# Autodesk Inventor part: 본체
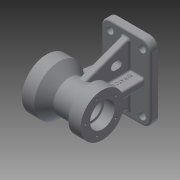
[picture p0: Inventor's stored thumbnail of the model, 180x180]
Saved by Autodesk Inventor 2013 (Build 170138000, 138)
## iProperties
Created: 2015-08
Part Number: 본체
Material: 알루미늄 6061
Document SubType Name: Modeling
Designer: dfdfd
Density: 2.71 g/cm^3
Mass: 1068.68 g
Surface Area: 796.751 cm^2
Volume: 394.348 cm^3
Author: dfdfd
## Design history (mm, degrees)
sketch "스케치2"
  geometry: L1 (0, 0)-(0, 35); L2 (0, 35)-(20, 35); L3 (20, 35)-(25.196, 26); L4 (25.196, 26)-(53.315, 26); L5 (53.315, 26)-(70, 40); L6 (70, 40)-(90, 40); L7 (90, 40)-(90, 0); L8 (90, 0)-(0, 0)
  constraints: 16 end point, 4 parallel, 1 perpendicular, 1 vertical
  dimensions: "d0" = 20 distance from line of L2.end L1; "d2" = 90 distance between parallel lines of L7 L1; "d3" = 20 distance from line of L7 L5.end; "d4" = 60 deg angle of L4 L3; "d5" = 40 deg angle of L4 L5; "d6" = 70 diameter of L2 L8; "d7" = 80 diameter of L6 L8; "d8" = 52 diameter of L4 L8
revolve "회전1" sketch "스케치2" stored, may be unused: angle "d9" = 90 deg
sketch "스케치3"
  geometry: L1 (0, 90)-(-80, 90); L2 (-80, 90)-(-80, 78); L3 (-80, 78)-(0, 78); L4 (0, 78)-(0, 90); L5 (0, -35)-(-20, -35) reference; L6 (-20, -35)-(-25.196, -26) reference; L7 (-25.196, -26)-(-53.315, -26) reference; L8 (-53.315, -26)-(-70, -40) reference; L9 (-70, -40)-(-90, -40) reference; L10 (-90, -40)-(-90, 40) reference; L11 (-90, 40)-(-70, 40) reference; L12 (-70, 40)-(-53.315, 26) reference; L13 (-53.315, 26)-(-25.196, 26) reference; L14 (-25.196, 26)-(-20, 35) reference; L15 (-20, 35)-(0, 35) reference; L16 (0, 35)-(0, -35) reference; 3 further points
  constraints: 8 end point, 2 midpoint, 2 parallel, 1 horizontal, 1 perpendicular, 1 vertical alignment
  dimensions: "d10" = 90 distance from line of L1 point (0, 0); "d11" = 12 distance between parallel lines of L1 L3; "d12" = 80 distance between parallel lines of L2 L4
extrude "돌출1" join sketch "스케치3" stored distance "d13" = 122; taper "d14" = 0 deg
sketch "스케치4"
  geometry: L1 (0, -35)-(-20, -35) reference; L2 (-20, -35)-(-25.196, -26) reference; L3 (-25.196, -26)-(-53.315, -26) reference; L4 (-53.315, -26)-(-70, -40) reference; L5 (-70, -40)-(-90, -40) reference; L6 (-90, -40)-(-90, 40) reference; L7 (-90, 40)-(-70, 40) reference; L8 (-70, 40)-(-53.315, 26) reference; L9 (-53.315, 26)-(-25.196, 26) reference; L10 (-25.196, 26)-(-20, 35) reference; L11 (-20, 35)-(0, 35) reference; L12 (0, 35)-(0, -35) reference; L13 (0, 90)-(0, 78) reference; L14 (0, 78)-(-80, 78) reference; L15 (-80, 78)-(-80, 90) reference; L16 (-80, 90)-(0, 90) reference; L17 (-70, 78)-(-76.7, 40); L18 (-10, 35)-(-10, 78); 1 further point
  constraints: 4 end point, 3 point on line, 1 midpoint, 1 perpendicular
  dimensions: "d17" = 10 distance between parallel lines of L13 L18; "d18" = 80 deg angle of L14 L17; "d19" = 10 distance from line of L15 L17.start
extrude "돌출2" join sketch "스케치4" stored distance "d20" = 12; taper "d21" = 0 deg
node "작업 평면1"
sketch "스케치5"
  geometry: L1 (90, -61)-(78, -61) reference; L2 (78, -61)-(78, -6) reference; L3 (78, -6)-(26, -6) reference; L4 (26, -6)-(26, 0) reference; L5 (26, 0)-(26, 6) reference; L6 (26, 6)-(78, 6) reference; L7 (78, 6)-(78, 61) reference; L8 (78, 61)-(90, 61) reference; L9 (90, 61)-(90, -61) reference; L10 (6.815, -25.091)-(78, -51); L11 (6.815, 25.091)-(78, 51); L12 (0, 0)-(113.141, 0); A1 r 26 centre (0, 0) between (26, 0) and (6.815, -25.091) reference; 1 further point
  constraints: 6 end point, 2 point on circle, 2 point on line, 1 perpendicular
  dimensions: "d23" = 70 deg angle of L11 L7; "d24" = 70 deg angle of L2 L10; "d25" = 10 distance from line of L1 L10.end; "d26" = 10 distance from line of L8 L11.end
extrude "돌출3" join sketch "스케치5" stored distance "d27" = 12; taper "d28" = 0 deg
hole "구멍1" diameter "d31" = 38; stored, may be unused: countersink angle "d35" = 90 deg, drill point angle "d37" = 0 deg; dims "d29" = 10, "d30" = 10, "d32" = 6, "d33" = 52, "d34" = 20, "d36" = 23
hole "구멍2" diameter "d40" = 32; stored, may be unused: countersink angle "d44" = 90 deg, drill point angle "d46" = 0 deg; dims "d38" = 10, "d39" = 10, "d41" = 6, "d42" = 40, "d43" = 17, "d45" = 67
sketch "스케치6" dims "d47" = 66
  geometry: C1 r 26 at (0, 0) reference; C2 r 40 at (0, 0) reference; 2 further points
  constraints: 2 vertical alignment, 1 coincident, 2 other
hole "구멍3" sketch "스케치6" at (0, -33) diameter "d48" = 3.242; stored, may be unused: countersink angle "d52" = 90 deg, drill point angle "d54" = 118 deg; dims "d49" = 10, "d50" = 40, "d51" = 17, "d53" = 13
sketch "스케치7" dims "d58" = 54
  geometry: C1 r 20 at (0, 0) reference; C2 r 35 at (0, 0) reference; 2 further points
  constraints: 2 vertical alignment, 1 coincident, 2 other
hole "구멍4" sketch "스케치7" at (0, -27) diameter "d59" = 3.242; stored, may be unused: countersink angle "d63" = 90 deg, drill point angle "d65" = 118 deg; dims "d60" = 10, "d61" = 40, "d62" = 17, "d64" = 13
sketch "스케치8"
  geometry: L1 (80, -122)-(80, 0) reference; L2 (0, 0)-(80, 0) reference; C1 r 6 at (66, -14); 1 further point
  constraints: 1 centre point
  dimensions: "d71" = 12 diameter of C1; "d74" = 14 distance from line of L2 C1.centre; "d75" = 14 distance from line of L1 C1.centre
extrude "돌출4" cut sketch "스케치8" stored distance "d76" = 12; taper "d77" = 0 deg
sketch "스케치9"
  geometry: L1 (6, 26)-(6, 78) reference; L2 (30, 54)-(30, 60); L3 (18, 60)-(18, 54); L4 (-61, 78)-(61, 78) reference; A1 r 26 centre (0, 0) between (25.091, 6.815) and (0, 26) reference; A2 r 6 centre (24, 60) between (30, 60) and (18, 60); A3 r 6 centre (24, 54) between (18, 54) and (30, 54)
  constraints: 4 end point, 4 point on circle, 3 tangent, 2 centre point, 2 parallel, 1 equal radius
  dimensions: "d78" = 12 distance between parallel lines of L2 L3; "d80" = 18 dimension on A2 A3; "d81" = 18 distance from line of L4 A2.centre; "d82" = 24 horizontal distance of A1.centre A2.centre
extrude "돌출5" cut sketch "스케치9" stored distance "d83" = 12; taper "d84" = 0 deg
sketch "스케치10"
  geometry: L1 (-10, 35)-(-10, 78) reference; L2 (0, 78)-(0, 90) reference; L3 (-80, 78)-(0, 78) reference; 2 further points
  constraints: 1 other
  dimensions: "d87" = 16 distance from line of L1 point (-26, 54); "d88" = 24 distance from line of L3 point (-26, 54)
feature "엠보싱1" sketch "스케치10" dims "d0" = 20, "d2" = 90, "d3" = 20, "d4" = 60 deg, "d5" = 40 deg, "d6" = 70, "d7" = 80, "d8" = 52, "d89" = 0.5, "d90" = 0
fillet "모깎기5" dims "d92" = 3
fillet "모깎기6" dims "d93" = 14
fillet "모깎기7" dims "d94" = 0.3
fillet "모깎기8" dims "d95" = 3
fillet "모깎기11" dims "d98" = 3
fillet "모깎기12" dims "d99" = 3
fillet "모깎기15" dims "d102" = 5
node "솔리드1"
pattern_circular "원형 패턴1" dims angle "d56" = 360 deg
pattern_circular "원형 패턴2" dims angle "d67" = 360 deg
mirror "대칭1"
mirror "대칭2"
mirror "대칭3"
node "절단 모서리 투영1"
node "절단 모서리 투영2"
node "절단 모서리 투영3"
